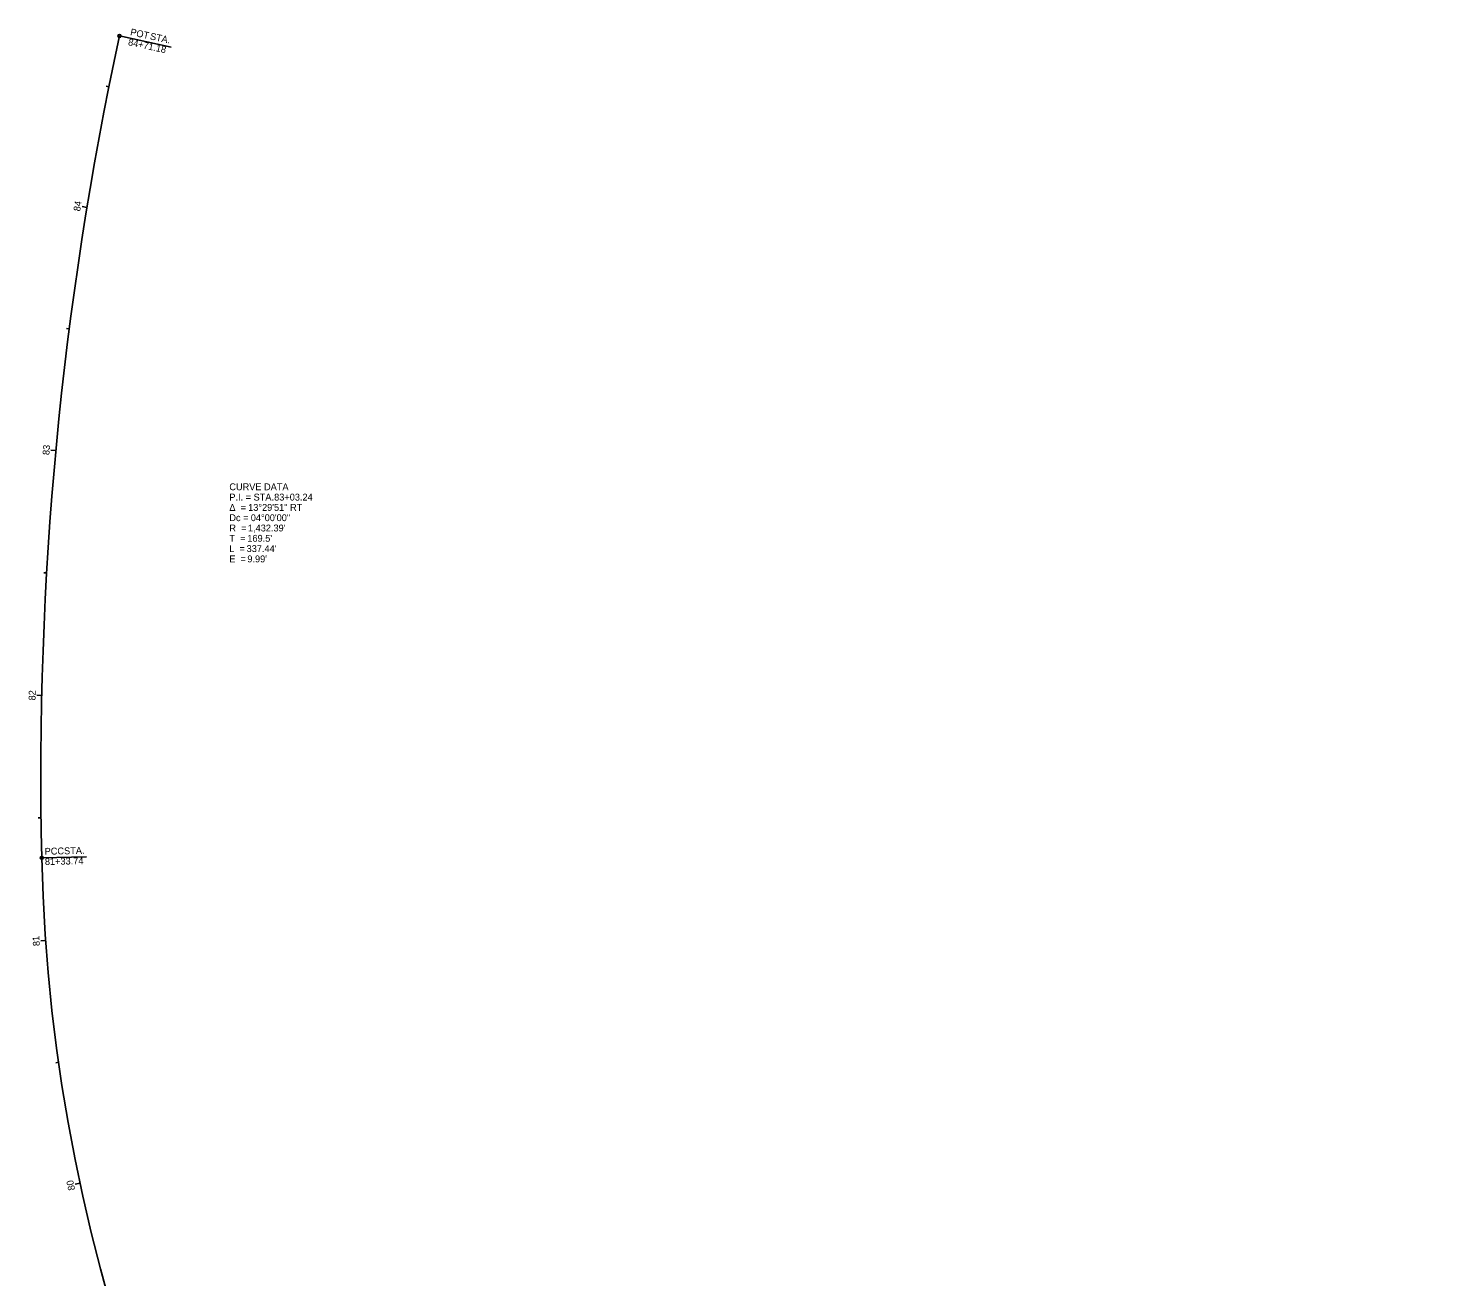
# Model space of a CAD drawing. Extents: x 2203357 to 2204663, y 635542 to 636605.
# Drawn here: x 2203357 to 2203939, y 636096 to 636605 of the extents above; entities that cross this region are included whole.
import ezdxf

# ---------------------------------------------------------------- set-up
doc = ezdxf.new("R2010")
doc.units = 0
for name, color, linetype in [('RW_X_CL', 7, 'Continuous'), ('SH_Border', 7, 'Continuous'), ('SH_Cut_Line', 7, 'Continuous'), ('SH_Data', 7, 'Continuous')]:
    doc.layers.add(name, color=color, linetype=linetype)

msp = doc.modelspace()

# ---------------------------------------------------------------- linework, layer by layer
at = {"layer": 'RW_X_CL'}
for p, q in [((2203389.44, 636581.12), (2203388.26, 636581.35)), ((2203380.5, 636531.92), (2203378.52, 636532.25)), ((2203373.28, 636482.45), (2203372.09, 636482.6)), ((2203367.79, 636432.76), (2203365.8, 636432.94)), ((2203364.05, 636382.9), (2203362.85, 636382.97)), ((2203362.04, 636332.94), (2203360.04, 636332.99)), ((2203361.78, 636282.94), (2203360.58, 636282.93)), ((2203363.66, 636232.99), (2203361.66, 636232.85)), ((2203368.93, 636183.28), (2203367.74, 636183.11)), ((2203377.65, 636134.05), (2203375.69, 636133.64))]:
    msp.add_line(p, q, dxfattribs=at)
at = {"layer": 'SH_Cut_Line'}
for centre, radius, start, end in [((2204794.06, 636300.44), 1432.39, 167.85294, 181.35056), ((2204794.06, 636300.44), 1432.39, 167.85294, 181.35056), ((2204078.07, 636283.56), 716.2, 181.35056, 258.76282), ((2204078.07, 636283.56), 716.2, 181.35056, 258.76282), ((2204078.07, 636283.56), 716.2, 181.35056, 258.76282)]:
    msp.add_arc(centre, radius, start, end, dxfattribs=at)
at = {"layer": 'SH_Data'}
for p, q in [((2203393.74, 636601.85), (2203414.88, 636597.3)), ((2203362.07, 636266.68), (2203380.34, 636267.11))]:
    msp.add_line(p, q, dxfattribs=at)
for centre in [(2203393.74, 636601.85), (2203362.07, 636266.68)]:
    msp.add_circle(centre, 0.6, dxfattribs=at)

# ---------------------------------------------------------------- texts
at = {"layer": 'RW_X_CL'}
for s, rotation, p in [('84', 80.69999, (2203377.68, 636530.2)), ('83', 84.69999, (2203365.11, 636430.84)), ('82', 88.69999, (2203359.49, 636330.84)), ('81', 94.04942, (2203361.31, 636230.78)), ('80', 102.04942, (2203375.67, 636131.35))]:
    msp.add_text(s, height=2.8, rotation=rotation, dxfattribs=at).set_placement(p)
at = {"layer": 'SH_Border'}
for s, p in [('CURVE DATA', (2203438.55, 636416.59)), ('P.I. = STA. ', (2203438.55, 636412.39)), ('83+03.24', (2203456.81, 636412.39)), ('Δ  = ', (2203438.55, 636408.19)), ('Dc = ', (2203438.55, 636403.99)), ('13°29\'51" RT', (2203446.22, 636408.19)), ('04°00\'00"', (2203447.29, 636403.99)), ('R  = ', (2203438.55, 636399.79)), ("1,432.39'", (2203446.13, 636399.79)), ('T  = ', (2203438.55, 636395.59)), ("169.5'", (2203445.88, 636395.59)), ('L  = ', (2203438.55, 636391.39)), ('E  = ', (2203438.55, 636387.19)), ("337.44'", (2203445.59, 636391.39)), ("9.99'", (2203445.89, 636387.19))]:
    msp.add_text(s, height=2.8, dxfattribs=at).set_placement(p)
at = {"layer": 'SH_Data'}
for s, rotation, p in [('POT', 347.85294, (2203397.96, 636602.22)), ('84+71.18', 347.85294, (2203397.08, 636598.11)), (' STA. ', 347.85294, (2203405, 636600.7)), ('81+33.74', 1.35056, (2203363.36, 636263.73)), ('PCC', 1.35056, (2203363.26, 636267.93)), (' STA. ', 1.35056, (2203370.15, 636268.09))]:
    msp.add_text(s, height=2.8, rotation=rotation, dxfattribs=at).set_placement(p)

doc.saveas('drawing.dxf')
